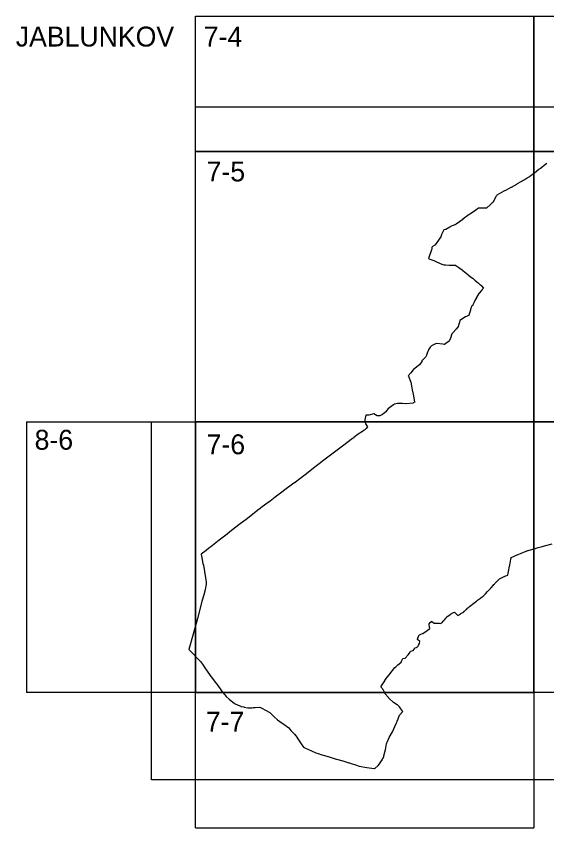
# Model space of a CAD drawing. Extents: x -447552 to -439754, y -1129367 to -1125104.
# Drawn here: x -443419.6 to -443174.5, y -1128953.4 to -1128578.4 of the extents above; entities that cross this region are included whole.
import ezdxf

# ---------------------------------------------------------------- set-up
doc = ezdxf.new("R2010")
doc.units = 0
for name, color, linetype in [('Vrstva 1', 7, 'Continuous'), ('Vrstva 10', 7, 'Continuous'), ('Vrstva 4', 7, 'Continuous')]:
    doc.layers.add(name, color=color, linetype=linetype)

msp = doc.modelspace()

# ---------------------------------------------------------------- linework, layer by layer
at = {"layer": 'Vrstva 1'}
for points in [[(-443174.45, -1128646.44), (-443175.66, -1128647.4), (-443175.66, -1128647.4), (-443176.81, -1128648.27), (-443177.38, -1128648.7), (-443177.96, -1128649.14), (-443178.12, -1128649.26), (-443180.25, -1128650.9), (-443181.32, -1128651.72), (-443181.79, -1128652.06), (-443182.55, -1128652.57), (-443182.8, -1128652.73), (-443183.39, -1128653.12), (-443183.43, -1128653.15), (-443183.64, -1128653.29), (-443184.55, -1128653.89), (-443184.56, -1128653.89), (-443185.03, -1128654.15), (-443185.18, -1128654.23), (-443185.36, -1128654.33), (-443185.82, -1128654.58), (-443186, -1128654.69), (-443186.16, -1128654.78), (-443186.26, -1128654.84), (-443186.5, -1128654.98), (-443188.16, -1128655.92), (-443188.33, -1128656.01), (-443188.56, -1128656.14), (-443191.03, -1128657.54), (-443191.15, -1128657.61), (-443193.26, -1128658.74), (-443194.28, -1128659.29), (-443197.62, -1128661.1), (-443197.79, -1128661.4), (-443197.85, -1128661.51), (-443198.63, -1128662.97), (-443199.31, -1128664.29), (-443199.45, -1128664.42), (-443199.54, -1128664.5), (-443200.68, -1128665.54), (-443202.19, -1128666.92), (-443202.36, -1128667.07), (-443202.36, -1128667.08), (-443202.83, -1128667.09), (-443206.02, -1128667.18), (-443206.03, -1128667.18), (-443206.46, -1128667.47), (-443207.29, -1128668.04), (-443209.76, -1128669.7), (-443209.8, -1128669.72), (-443210.04, -1128669.9), (-443210.31, -1128670.1), (-443213.29, -1128672.23), (-443213.36, -1128672.28), (-443216.36, -1128674.46), (-443216.83, -1128674.8), (-443216.99, -1128674.86), (-443218.93, -1128675.58), (-443218.94, -1128675.58), (-443219.33, -1128675.82), (-443221.21, -1128676.98), (-443222.13, -1128677.19), (-443222.38, -1128677.7), (-443223.14, -1128679.21), (-443223.15, -1128679.22), (-443223.22, -1128679.48), (-443223.42, -1128680.32), (-443224.25, -1128681.43), (-443225.62, -1128683.38), (-443226.18, -1128684.19), (-443226.21, -1128684.21), (-443227.37, -1128684.85), (-443227.47, -1128684.91), (-443227.54, -1128685.3), (-443227.69, -1128686.11), (-443227.74, -1128686.3), (-443229.03, -1128689.88), (-443229.2, -1128690.36), (-443229.17, -1128690.35), (-443229.15, -1128690.34), (-443228.47, -1128690.6), (-443226.66, -1128691.26), (-443226.04, -1128691.55), (-443223.75, -1128692.63), (-443223.73, -1128692.63), (-443222.57, -1128693.1), (-443222.1, -1128693.28), (-443222.07, -1128693.29), (-443221.64, -1128693.32), (-443221.5, -1128693.33), (-443221.28, -1128693.35), (-443219.68, -1128693.45), (-443218.64, -1128693.52), (-443217.59, -1128693.49), (-443216.75, -1128693.46), (-443216.74, -1128693.46), (-443216.46, -1128693.61), (-443216.09, -1128693.87), (-443215.54, -1128694.25), (-443215.15, -1128694.53), (-443213.59, -1128695.67), (-443213.42, -1128695.79), (-443212.31, -1128696.71), (-443211.92, -1128697.03), (-443211.74, -1128697.18), (-443210.99, -1128697.79), (-443210.72, -1128698.02), (-443210.12, -1128698.51), (-443209.9, -1128698.69), (-443209.26, -1128699.11), (-443208.51, -1128699.61), (-443208.48, -1128699.63), (-443207.72, -1128700.31), (-443206.84, -1128701.09), (-443206.4, -1128701.47), (-443205.39, -1128702.36), (-443205.13, -1128702.59), (-443205.08, -1128702.64), (-443204.98, -1128702.74), (-443204.97, -1128702.75), (-443204.88, -1128702.85), (-443204.85, -1128702.88), (-443203.8, -1128704.11), (-443203.81, -1128704.12), (-443204.25, -1128704.61), (-443204.31, -1128704.68), (-443204.88, -1128705.31), (-443205.7, -1128706.37), (-443205.87, -1128706.58), (-443206.43, -1128707.3), (-443206.73, -1128707.83), (-443206.75, -1128707.87), (-443206.76, -1128707.89), (-443206.89, -1128708.17), (-443207.69, -1128709.84), (-443208, -1128710.48), (-443208.62, -1128711.77), (-443208.73, -1128712.01), (-443208.74, -1128712.01), (-443208.78, -1128712.04), (-443209.07, -1128712.24), (-443209.15, -1128712.28), (-443209.2, -1128712.38), (-443209.29, -1128712.58), (-443209.38, -1128712.86), (-443209.55, -1128713.42), (-443209.56, -1128713.44), (-443209.68, -1128713.94), (-443209.7, -1128714.01), (-443209.69, -1128714.07), (-443209.68, -1128714.15), (-443209.68, -1128714.22), (-443209.69, -1128714.27), (-443210.57, -1128716.6), (-443210.59, -1128716.65), (-443210.61, -1128716.69), (-443210.62, -1128716.7), (-443211.32, -1128717), (-443211.57, -1128717.11), (-443212.04, -1128717.35), (-443214.65, -1128719.04), (-443214.65, -1128719.04), (-443215.02, -1128720.35), (-443215.1, -1128720.61), (-443215.21, -1128721.03), (-443215.27, -1128721.24), (-443215.27, -1128721.25), (-443215.26, -1128721.25), (-443215.09, -1128721.41), (-443215.1, -1128721.42), (-443215.46, -1128721.81), (-443216.26, -1128722.81), (-443216.27, -1128722.82), (-443216.48, -1128723.07), (-443216.48, -1128723.08), (-443216.6, -1128723.23), (-443217.76, -1128724.58), (-443218.3, -1128725.21), (-443219.06, -1128727.16), (-443219.44, -1128728.18), (-443219.57, -1128728.53), (-443221.1, -1128729.63), (-443221.72, -1128730.07), (-443221.9, -1128730.11), (-443221.92, -1128730.11), (-443222.55, -1128730.02), (-443225.39, -1128729.6), (-443225.88, -1128729.84), (-443227.21, -1128730.48), (-443227.75, -1128730.74), (-443227.78, -1128730.77), (-443228.21, -1128731.18), (-443228.38, -1128731.4), (-443229.04, -1128732.25), (-443229.04, -1128732.26), (-443229.71, -1128734.06), (-443230.28, -1128735.56), (-443230.28, -1128735.56), (-443230.42, -1128735.78), (-443230.75, -1128736.15), (-443231.47, -1128736.95), (-443232.17, -1128737.72), (-443232.18, -1128737.74), (-443232.31, -1128737.93), (-443233.38, -1128739.5), (-443233.85, -1128739.88), (-443235.42, -1128741.14), (-443236.09, -1128741.68), (-443236.19, -1128741.76), (-443236.22, -1128741.8), (-443237.34, -1128743.23), (-443238.48, -1128744.54), (-443238.33, -1128744.71), (-443238.32, -1128744.74), (-443238.32, -1128744.75), (-443237.31, -1128747.51), (-443237.03, -1128749.17), (-443236.71, -1128751.12), (-443236.3, -1128753.08), (-443235.57, -1128756.58), (-443235.53, -1128756.78), (-443236.18, -1128757.12), (-443236.3, -1128757.19), (-443239.47, -1128757.45), (-443239.63, -1128757.45), (-443241.12, -1128757.42), (-443243.51, -1128757.4), (-443244.79, -1128757.67), (-443245.39, -1128757.94), (-443246.37, -1128758.74), (-443247.67, -1128759.61), (-443247.76, -1128759.72), (-443248.92, -1128761.14), (-443250.37, -1128762.48), (-443251.06, -1128762.8), (-443251.66, -1128763.08), (-443252.83, -1128763.01), (-443254.44, -1128762.16), (-443256.68, -1128762.83), (-443258.16, -1128762.8), (-443258.54, -1128764.91), (-443258.55, -1128764.93), (-443258.56, -1128765.02), (-443258.27, -1128766.83), (-443257.3, -1128768.15), (-443257.29, -1128768.17), (-443258.03, -1128768.92), (-443258.64, -1128769.48), (-443258.89, -1128769.71), (-443259.69, -1128770.34), (-443261.62, -1128771.57), (-443261.68, -1128771.61), (-443263.65, -1128773.14), (-443263.71, -1128773.18), (-443264.2, -1128773.56), (-443268.86, -1128777.02), (-443268.89, -1128777.05), (-443273.84, -1128780.81), (-443278.1, -1128784.06), (-443278.98, -1128784.72), (-443281.55, -1128786.66), (-443285.55, -1128789.79), (-443287.99, -1128791.66), (-443291.3, -1128794.19), (-443291.35, -1128794.23), (-443296.14, -1128797.74), (-443296.37, -1128797.92), (-443299.98, -1128800.6), (-443302.37, -1128802.42), (-443304.34, -1128803.9), (-443306.66, -1128805.65), (-443306.89, -1128805.82), (-443308.02, -1128806.71), (-443312.84, -1128810.51), (-443316.73, -1128813.46), (-443320.95, -1128816.71), (-443322.24, -1128817.71), (-443324.63, -1128819.59), (-443325.81, -1128820.51), (-443329.75, -1128823.56), (-443330.68, -1128824.27), (-443331.92, -1128825.23), (-443334.24, -1128827.03), (-443334.24, -1128827.03), (-443334.2, -1128827.21), (-443333.91, -1128828.59), (-443333.88, -1128828.75), (-443333.35, -1128831.29), (-443333.19, -1128832.02), (-443333.19, -1128832.06), (-443332.26, -1128837.94), (-443332.25, -1128837.97), (-443331.95, -1128839.7), (-443331.95, -1128839.72), (-443331.89, -1128840.09), (-443331.83, -1128840.51), (-443331.86, -1128840.88), (-443332.01, -1128841.61), (-443332.39, -1128843.4), (-443332.68, -1128844.58), (-443332.7, -1128844.63), (-443333.81, -1128848.8), (-443335.91, -1128856.68), (-443337.9, -1128863.9), (-443339.83, -1128871), (-443339.84, -1128871.04), (-443334.56, -1128876.64), (-443333.51, -1128877.77), (-443332.75, -1128878.99), (-443330.73, -1128882.05), (-443330.68, -1128882.12), (-443329.67, -1128883.53), (-443329.51, -1128883.74), (-443327.63, -1128886.22), (-443327.06, -1128886.96), (-443327.03, -1128887), (-443326.51, -1128887.72), (-443325.13, -1128889.62), (-443324.8, -1128890.07), (-443322.65, -1128892.79), (-443321.25, -1128894.01), (-443318.85, -1128895.99), (-443317.11, -1128896.74), (-443315.92, -1128897.26), (-443315.79, -1128897.31), (-443314.46, -1128897.59), (-443314.32, -1128897.62), (-443312.7, -1128897.95), (-443312.67, -1128897.95), (-443311.71, -1128897.93), (-443311.33, -1128897.93), (-443310.81, -1128897.92), (-443310.13, -1128897.91), (-443309.22, -1128897.87), (-443307.27, -1128897.71), (-443306.82, -1128897.78), (-443306.16, -1128898.13), (-443304.44, -1128899.08), (-443302.48, -1128900.18), (-443301.96, -1128900.66), (-443301.24, -1128901.34), (-443300.44, -1128902.09), (-443299.12, -1128903.39), (-443298.98, -1128903.49), (-443297.79, -1128904.34), (-443295.38, -1128906.05), (-443293.74, -1128907.23), (-443292.69, -1128908.41), (-443291.05, -1128910.23), (-443290.41, -1128910.94), (-443290.05, -1128911.53), (-443289.59, -1128912.27), (-443288.65, -1128913.74), (-443288.02, -1128914.66), (-443286.98, -1128916.1), (-443285.91, -1128916.61), (-443284.53, -1128917.26), (-443283.22, -1128917.87), (-443281.25, -1128918.76), (-443280.12, -1128919.11), (-443278.4, -1128919.68), (-443278.25, -1128919.73), (-443277.16, -1128920.05), (-443275.74, -1128920.47), (-443275.73, -1128920.47), (-443275.52, -1128920.53), (-443275.46, -1128920.55), (-443274.6, -1128920.81), (-443272.21, -1128921.5), (-443272.09, -1128921.54), (-443271.61, -1128921.68), (-443268.68, -1128922.55), (-443265.99, -1128923.38), (-443265.65, -1128923.48), (-443264.89, -1128923.71), (-443262.88, -1128924.33), (-443261.15, -1128924.88), (-443257.69, -1128925.62)], [(-443257.69, -1128925.62), (-443255.3, -1128925.81), (-443254.1, -1128926.04), (-443253.99, -1128925.95), (-443252.41, -1128924.68), (-443251.38, -1128923.2), (-443251.27, -1128923.05), (-443250.75, -1128922.29), (-443250.64, -1128922.12), (-443250.5, -1128921.89), (-443250.12, -1128921.26), (-443249.85, -1128920.43), (-443249.83, -1128920.36), (-443249.81, -1128920.31), (-443249.78, -1128920.2), (-443249.75, -1128920.11), (-443249.75, -1128920.1), (-443249.12, -1128917.9), (-443248.98, -1128917.38), (-443248.53, -1128914.63), (-443248.53, -1128914.63), (-443248.34, -1128914.19), (-443248.08, -1128913.57), (-443247.29, -1128911.74), (-443245.72, -1128909.09), (-443243.97, -1128904.96), (-443243.65, -1128904.32), (-443243.61, -1128904.19), (-443243.22, -1128903.09), (-443242.63, -1128901.42), (-443240.95, -1128899.71), (-443241.88, -1128898.47), (-443241.94, -1128898.38), (-443241.99, -1128898.32), (-443242.02, -1128898.28), (-443242.09, -1128898.18), (-443242.14, -1128898.1), (-443242.22, -1128897.98), (-443242.58, -1128897.46), (-443242.95, -1128897), (-443243.52, -1128896.63), (-443243.62, -1128896.57), (-443245.27, -1128895.5), (-443247.46, -1128893.56), (-443247.59, -1128893.39), (-443247.62, -1128893.35), (-443247.7, -1128893.25), (-443248.04, -1128892.83), (-443248.37, -1128892.42), (-443248.63, -1128892.1), (-443249.11, -1128891.51), (-443249.19, -1128891.41), (-443249.69, -1128890.45), (-443249.98, -1128889.89), (-443250.21, -1128889.46), (-443250.26, -1128889.37), (-443250.3, -1128889.32), (-443250.56, -1128889.03), (-443250.76, -1128888.8), (-443251.02, -1128888.51), (-443251.24, -1128888.26), (-443249.38, -1128885.52), (-443249.29, -1128885.4), (-443248.97, -1128884.95), (-443248.65, -1128884.51), (-443247.32, -1128882.68), (-443244.64, -1128879.42), (-443244.29, -1128879.1), (-443243.58, -1128878.4), (-443243.47, -1128878.31), (-443243.28, -1128878.17), (-443242.68, -1128877.69), (-443241.82, -1128876.85), (-443241.41, -1128876.09), (-443240.94, -1128875.22), (-443239.89, -1128874.98), (-443238.49, -1128873.55), (-443237.95, -1128872.7), (-443237.94, -1128872.69), (-443237.94, -1128872.67), (-443237.73, -1128872.34), (-443237.68, -1128872.26), (-443237.44, -1128871.87), (-443236.28, -1128871.43), (-443235.26, -1128870.25), (-443234.73, -1128870.05), (-443234.61, -1128870), (-443234.19, -1128869.84), (-443233.97, -1128869.45), (-443233.92, -1128869.36), (-443233.75, -1128869.06), (-443233.34, -1128868.32), (-443233.14, -1128867.41), (-443233.14, -1128867.39), (-443233.13, -1128867.38), (-443234.18, -1128866.39), (-443234.2, -1128866.38), (-443234.21, -1128866.36), (-443234.26, -1128866.32), (-443233.61, -1128864.52), (-443233.54, -1128864.32), (-443233.38, -1128864.26), (-443232.65, -1128863.97), (-443231.96, -1128863.7), (-443231.84, -1128863.65), (-443230.63, -1128862.94), (-443230.51, -1128862.86), (-443230.51, -1128862.86), (-443230.5, -1128862.85), (-443230.38, -1128862.78), (-443228.52, -1128861.38), (-443228.52, -1128861.34), (-443228.55, -1128861.18), (-443228.62, -1128860.7), (-443228.68, -1128860.35), (-443228.78, -1128859.73), (-443228.8, -1128859.62), (-443228.82, -1128859.49), (-443228.84, -1128859.32), (-443228.87, -1128859.18), (-443228.33, -1128858.62), (-443227.77, -1128858.05), (-443227.73, -1128858), (-443227.59, -1128858.1), (-443226.59, -1128858.89), (-443225.91, -1128858.9), (-443225.85, -1128858.9), (-443225.6, -1128858.91), (-443225.44, -1128858.91), (-443224.13, -1128858.93), (-443223.5, -1128858.95), (-443223.23, -1128858.79), (-443223.2, -1128858.77), (-443223.08, -1128858.7), (-443222.94, -1128858.61), (-443222.9, -1128858.58), (-443222.36, -1128857.98), (-443222.25, -1128857.86), (-443222.16, -1128857.76), (-443221.99, -1128857.58), (-443221.91, -1128857.49), (-443221.8, -1128857.37), (-443221.77, -1128857.33), (-443221.74, -1128857.3), (-443221.69, -1128857.24), (-443221.6, -1128857.13), (-443221.2, -1128856.63), (-443220.99, -1128856.37), (-443220.74, -1128856.05), (-443220.63, -1128855.97), (-443219.17, -1128854.9), (-443218.96, -1128854.77), (-443217.6, -1128854), (-443217.2, -1128853.77), (-443217.2, -1128853.77), (-443217.06, -1128853.92), (-443216.35, -1128854.63), (-443215.98, -1128855.01), (-443215.8, -1128855.18), (-443215.65, -1128855.33), (-443215.56, -1128855.29), (-443214.28, -1128854.52), (-443214.19, -1128854.47), (-443213.26, -1128853.91), (-443213.22, -1128853.88), (-443212.89, -1128853.59), (-443212.84, -1128853.55), (-443212.67, -1128853.4), (-443212.66, -1128853.39), (-443212.66, -1128853.39), (-443212.62, -1128853.35), (-443212.58, -1128853.31), (-443211.69, -1128852.5), (-443211.67, -1128852.49), (-443211.08, -1128851.95), (-443210.97, -1128851.86), (-443210.86, -1128851.76), (-443210.86, -1128851.76), (-443210.85, -1128851.76), (-443210.85, -1128851.76), (-443210.85, -1128851.75), (-443210.84, -1128851.75), (-443210.83, -1128851.74), (-443210.83, -1128851.74), (-443210.82, -1128851.73), (-443210.82, -1128851.73), (-443210.81, -1128851.73), (-443210.81, -1128851.73), (-443210.23, -1128851.24), (-443208.24, -1128849.56), (-443207.04, -1128848.71), (-443206.92, -1128848.63), (-443206.87, -1128848.59), (-443206.85, -1128848.58), (-443206.8, -1128848.55), (-443206.44, -1128848.28), (-443205.2, -1128847.34), (-443205.02, -1128847.2), (-443204.81, -1128847.04), (-443204.79, -1128847.02), (-443203.91, -1128846.35), (-443203.56, -1128846.08), (-443203.51, -1128846.02), (-443203.42, -1128845.92), (-443202.78, -1128845.24), (-443201.88, -1128844.26), (-443200.52, -1128842.85), (-443200.3, -1128842.62), (-443200.05, -1128842.34), (-443199.21, -1128841.39), (-443198.92, -1128841.07), (-443198.72, -1128840.86), (-443198.43, -1128840.54), (-443197.25, -1128839.35), (-443196.32, -1128838.33), (-443194.26, -1128837.32), (-443194.1, -1128837.27), (-443193.9, -1128837.19), (-443192.46, -1128836.7), (-443192.31, -1128835.83), (-443192.15, -1128834.96), (-443191.73, -1128832.59), (-443191.65, -1128832.12), (-443191.32, -1128830.24), (-443191.12, -1128829.36), (-443191.09, -1128829.24), (-443191.04, -1128829.05), (-443191.03, -1128829.01), (-443191.01, -1128828.94), (-443191, -1128828.9), (-443190.99, -1128828.85), (-443190.98, -1128828.81), (-443190.97, -1128828.79), (-443190.91, -1128828.58), (-443189.83, -1128828.04), (-443189.54, -1128827.9), (-443189.52, -1128827.89), (-443189.27, -1128827.76), (-443189.22, -1128827.74), (-443187.45, -1128827.02), (-443187.42, -1128827.01), (-443187.39, -1128826.99), (-443186.59, -1128826.68), (-443185.63, -1128826.28), (-443184.82, -1128825.94), (-443183.88, -1128825.55), (-443183.8, -1128825.52), (-443183.19, -1128825.28), (-443183.34, -1128825.44), (-443183.1, -1128825.35), (-443182.61, -1128825.15), (-443182.08, -1128824.99), (-443180.38, -1128824.47), (-443179.79, -1128824.3), (-443179.34, -1128824.18), (-443178.45, -1128823.93), (-443177.14, -1128823.55), (-443175.6, -1128823.09), (-443172.06, -1128822.22)]]:
    msp.add_lwpolyline(points, dxfattribs=at)
at = {"layer": 'Vrstva 10'}
msp.add_lwpolyline([(-443024.3, -1128620.23), (-443024.3, -1128931.21), (-443357.17, -1128931.21), (-443357.17, -1128765.91), (-443336.8, -1128765.91), (-443336.8, -1128640.91), (-443336.8, -1128620.23), (-443024.3, -1128620.23)], dxfattribs=at)
at = {"layer": 'Vrstva 4'}
for p, q in [((-443336.8, -1128578.41), (-443024.3, -1128578.41)), ((-443414.93, -1128765.91), (-443414.93, -1128890.91)), ((-443336.8, -1128953.41), (-443180.55, -1128953.41))]:
    msp.add_line(p, q, dxfattribs=at)
for points in [[(-443180.55, -1128578.41), (-443180.55, -1128640.91), (-443336.8, -1128640.91), (-443336.8, -1128578.41)], [(-443024.3, -1128578.41), (-443024.3, -1128640.91), (-443180.55, -1128640.91), (-443180.55, -1128578.41)], [(-443414.93, -1128765.91), (-443336.8, -1128765.91), (-443336.8, -1128890.91), (-443414.93, -1128890.91)], [(-443336.8, -1128953.41), (-443336.8, -1128890.91), (-443180.55, -1128890.91), (-443180.55, -1128953.41)]]:
    msp.add_lwpolyline(points, dxfattribs=at)
for points in [[(-443180.55, -1128640.91), (-443180.55, -1128765.91), (-443336.8, -1128765.91), (-443336.8, -1128640.91)], [(-443024.3, -1128640.91), (-443024.3, -1128765.91), (-443180.55, -1128765.91), (-443180.55, -1128640.91)], [(-443180.55, -1128765.91), (-443180.55, -1128890.91), (-443336.8, -1128890.91), (-443336.8, -1128765.91)], [(-443024.3, -1128765.91), (-443024.3, -1128890.91), (-443180.55, -1128890.91), (-443180.55, -1128765.91)]]:
    msp.add_lwpolyline(points, close=True, dxfattribs=at)

# ---------------------------------------------------------------- texts
at = {"layer": 'Vrstva 1'}
for s, p in [('JABLUNKOV', (-443419.84, -1128592.41)), ('7-4', (-443332.99, -1128592.41)), ('7-5', (-443331.68, -1128654.75)), ('8-6', (-443411.15, -1128778.72)), ('7-6', (-443331.68, -1128780.82)), ('7-7', (-443332.04, -1128908.99))]:
    msp.add_text(s, height=9.2, dxfattribs=at).set_placement(p)

doc.saveas('drawing.dxf')
